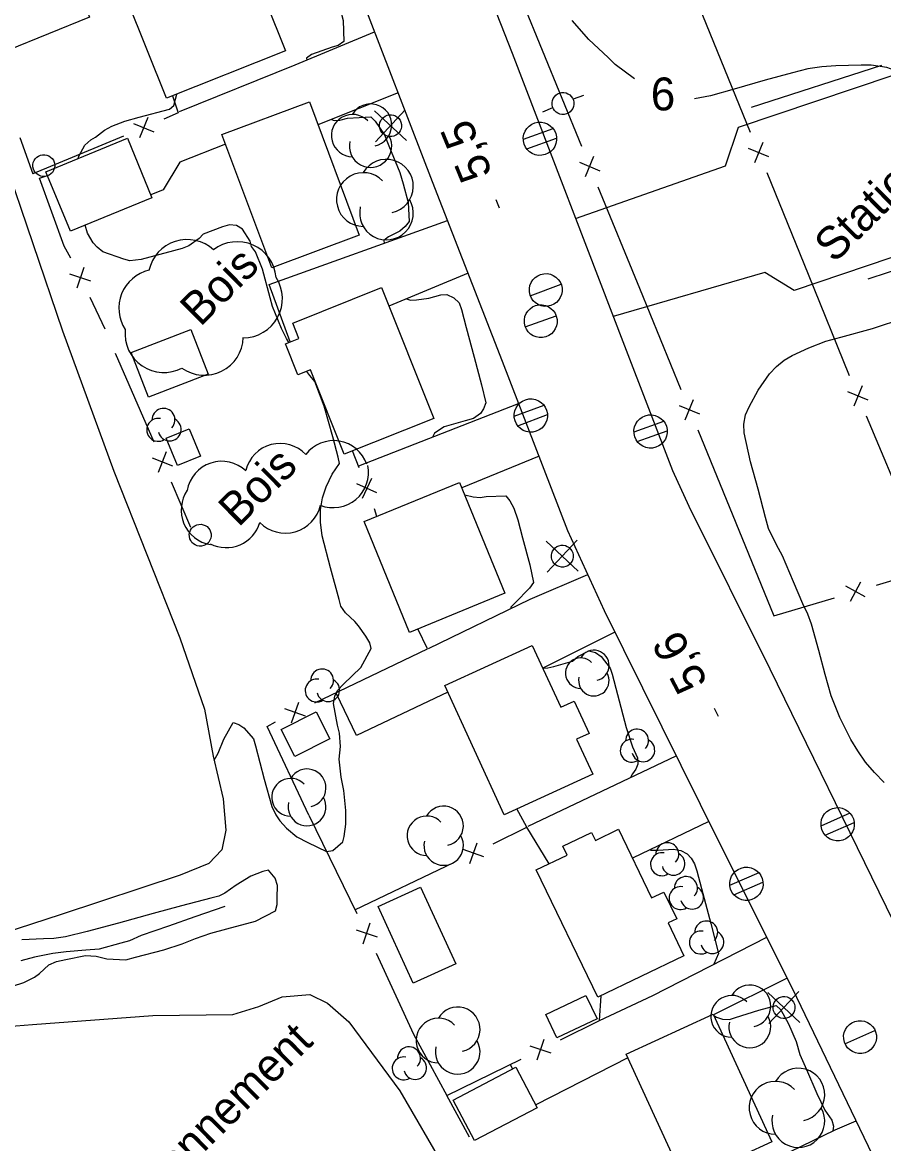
# Model space of a CAD drawing. Extents: x 381879 to 384696, y 5564785 to 5567594.
# Drawn here: x 383743.2 to 383821.8, y 5566686.3 to 5566788.7 of the extents above; entities that cross this region are included whole.
import ezdxf

# ---------------------------------------------------------------- set-up
doc = ezdxf.new("R2010")
doc.units = 0
for name, color, linetype in [('Niveau 19', 7, 'Continuous'), ('Niveau 2', 7, 'Continuous'), ('Niveau 21', 7, 'Continuous'), ('Niveau 3', 7, 'Continuous'), ('Niveau 31', 7, 'Continuous'), ('Niveau 36', 7, 'Continuous'), ('Niveau 37', 7, 'Continuous'), ('Niveau 4', 7, 'Continuous'), ('Niveau 44', 7, 'Continuous'), ('Niveau 52', 7, 'Continuous')]:
    doc.layers.add(name, color=color, linetype=linetype)

msp = doc.modelspace()

# ---------------------------------------------------------------- linework, layer by layer
at = {"layer": 'Niveau 19'}
for points in [[(383757.5, 5566780.56), (383768.08, 5566784.8), (383775.32, 5566787.83)], [(383777.47, 5566782.25), (383770.15, 5566779.33)], [(383761.7, 5566777.57), (383757.54, 5566775.93), (383756.02, 5566773.39), (383754.88, 5566772.94)], [(383767.62, 5566759.51), (383765.69, 5566764.76), (383781.98, 5566770.59)], [(383783.85, 5566765.78), (383776.63, 5566762.76)], [(383773.87, 5566748.19), (383788.46, 5566753.9), (383788.46, 5566753.9)], [(383790.33, 5566749.07), (383783.28, 5566746.18)], [(383780.23, 5566731.51), (383789.52, 5566736.01), (383794.78, 5566738.27)], [(383797.26, 5566733), (383790.67, 5566729.72)], [(383782.01, 5566727.52), (383773.66, 5566723.58), (383771.83, 5566727.38)], [(383789.34, 5566715.29), (383802.86, 5566721.72)], [(383805.84, 5566715.72), (383798.86, 5566712.36)], [(383812.97, 5566701.43), (383806.26, 5566698.06)], [(383798.43, 5566694.14), (383790.03, 5566689.84)], [(383787.91, 5566693.13), (383787.73, 5566693.55)], [(383817.37, 5566687.58), (383819.28, 5566688.39)]]:
    msp.add_lwpolyline(points, dxfattribs=at)
at = {"layer": 'Niveau 2'}
for points in [[(383764.66, 5566792.39), (383765.01, 5566792.5), (383767.2, 5566793.5), (383767.74, 5566793.73), (383768.88, 5566794.04), (383770.46, 5566794.33), (383770.92, 5566793.92), (383771.2, 5566793.42), (383771.41, 5566792.81), (383771.75, 5566791.53), (383772.44, 5566788.86), (383772.5, 5566786.93), (383772, 5566786.57), (383771.44, 5566786.42), (383769.57, 5566785.75), (383769.1, 5566785.42), (383769.12, 5566785.24)], [(383799.03, 5566783.54), (383797.29, 5566784.85), (383796.65, 5566785.47), (383794.88, 5566787.12), (383793.34, 5566788.86)], [(383822.9, 5566783.96), (383822.76, 5566784.32), (383822.09, 5566784.56), (383820.65, 5566784.77), (383819.74, 5566784.78), (383817.41, 5566784.73), (383816.13, 5566784.64), (383814.88, 5566784.45), (383813.46, 5566784.09), (383810.97, 5566783.42), (383808.13, 5566782.58), (383805.97, 5566781.98), (383804.53, 5566781.71)], [(383748.26, 5566776.26), (383748.31, 5566776.47), (383748.86, 5566777.49), (383749.4, 5566777.97), (383749.85, 5566778.21), (383750.65, 5566778.84), (383751.32, 5566779.21), (383752.52, 5566779.67), (383753.82, 5566780.02), (383756.58, 5566780.76), (383756.99, 5566781.1), (383757.15, 5566781.66), (383757.26, 5566782.13)], [(383771.38, 5566779.82), (383771.64, 5566779.72), (383772.15, 5566779.76), (383772.84, 5566779.94), (383774.97, 5566780.05), (383775.36, 5566779.66), (383776.21, 5566778.42), (383776.63, 5566777.4), (383777.61, 5566774.97), (383777.93, 5566773.95), (383778.38, 5566772.25), (383778.46, 5566770.51), (383778.1, 5566770.05), (383777.62, 5566769.63), (383776.59, 5566769.12), (383776.17, 5566768.78), (383776.19, 5566768.52)], [(383767.48, 5566759.45), (383767.26, 5566759.81), (383766.83, 5566760.75), (383766.01, 5566762.73), (383765.79, 5566763.54), (383765.09, 5566766.14), (383764.44, 5566767.73), (383764.08, 5566768.21), (383763.95, 5566768.72), (383763.26, 5566769.82), (383762.7, 5566770.14), (383762.08, 5566770.2), (383761.42, 5566770.03), (383759.66, 5566769.35), (383759.29, 5566768.94), (383758.35, 5566768.29), (383757.75, 5566768.03), (383756.96, 5566767.82), (383754.02, 5566767.03), (383752.96, 5566766.91), (383752.44, 5566767.08), (383750.52, 5566767.75), (383750, 5566768.15), (383749.64, 5566768.55), (383749.11, 5566769.44), (383748.91, 5566770.17)], [(383778.24, 5566763.43), (383778.6, 5566763.33), (383779.13, 5566763.34), (383780.27, 5566763.52), (383781.37, 5566763.82), (383781.92, 5566763.84), (383782.54, 5566763.55), (383783.04, 5566763.07), (383783.24, 5566762.46), (383783.68, 5566760.83), (383784.4, 5566758.13), (383785.08, 5566755.6), (383785.46, 5566753.96), (383785.27, 5566753.41), (383784.98, 5566752.98), (383784.35, 5566752.53), (383783.57, 5566752.29), (383781.66, 5566751.76), (383780.78, 5566751.18), (383780.6, 5566750.82)], [(383821.84, 5566719.29), (383820.95, 5566720.19), (383820.14, 5566721.15), (383819.43, 5566722.16), (383818.8, 5566723.2), (383817.78, 5566725.22), (383817, 5566727.21), (383816.45, 5566729.13), (383815.86, 5566731.33), (383815.21, 5566733.75), (383814.87, 5566734.65), (383814.42, 5566735.61), (383813.57, 5566737.61), (383812.54, 5566739.99), (383812.01, 5566740.98), (383811.28, 5566742.47), (383811.01, 5566743.47), (383810.32, 5566746.06), (383809.64, 5566748.57), (383809.04, 5566751.2), (383809.02, 5566751.99), (383809.18, 5566752.84), (383809.5, 5566753.58), (383810.34, 5566755.09), (383811.37, 5566756.59), (383812, 5566757.26), (383812.71, 5566757.84), (383813.44, 5566758.26), (383814.97, 5566758.98), (383816.51, 5566759.58), (383817.88, 5566759.95), (383820.77, 5566760.75), (383823.71, 5566761.7)], [(383761.55, 5566723.25), (383762.41, 5566724.76), (383762.91, 5566724.58), (383763.37, 5566724.27), (383764.26, 5566723.27), (383764.43, 5566722.63), (383765.24, 5566719.6), (383765.94, 5566717.09), (383766.29, 5566716.32), (383766.66, 5566715.79), (383767.27, 5566715.11), (383768.21, 5566714.33), (383769.22, 5566713.81), (383770.93, 5566712.98), (383771.51, 5566713.06), (383772.41, 5566713.86), (383772.55, 5566714.35), (383772.7, 5566715.49), (383772.68, 5566716.74), (383772.5, 5566718.54), (383772.26, 5566719.78), (383772.09, 5566721.41), (383772.21, 5566722.56), (383772.12, 5566723.78), (383771.92, 5566724.51), (383771.57, 5566726.51), (383771.7, 5566727.17), (383771.94, 5566727.69), (383772.49, 5566728.27), (383774.05, 5566729.78), (383775.01, 5566731.53), (383774.87, 5566732.05), (383774.52, 5566732.64), (383773.86, 5566733.58), (383773.5, 5566733.99), (383772.65, 5566734.77), (383772.24, 5566735.39), (383772.07, 5566736), (383771.3, 5566738.88), (383770.54, 5566741.79), (383770.37, 5566743.04), (383770.39, 5566744.19), (383770.56, 5566745.27), (383770.89, 5566746.29), (383771.45, 5566747.43), (383772.12, 5566748.42), (383771.98, 5566749), (383771.49, 5566750.84), (383770.72, 5566753.64), (383769.86, 5566755.91), (383769.39, 5566756.43), (383769.13, 5566756.81)], [(383783.54, 5566745.56), (383784.3, 5566745.37), (383784.96, 5566745.3), (383785.5, 5566745.4), (383787.3, 5566745.45), (383787.67, 5566745.01), (383788.02, 5566744.34), (383788.38, 5566743.27), (383788.82, 5566741.63), (383789.49, 5566739.16), (383789.83, 5566737.55), (383789.46, 5566737.02), (383788.16, 5566735.68), (383787.75, 5566735.28), (383787.74, 5566735.15)], [(383790.69, 5566729.73), (383791.12, 5566729.74), (383791.67, 5566729.87), (383793.39, 5566730.37), (383793.86, 5566730.79), (383794.88, 5566731.31), (383795.49, 5566731.14), (383795.99, 5566730.8), (383796.82, 5566729.73), (383796.99, 5566729.18), (383797.48, 5566727.33), (383798.29, 5566724.31), (383798.87, 5566722.54), (383799.32, 5566721.54), (383799.35, 5566720.97), (383799.17, 5566720.49)], [(383760.66, 5566721.32), (383761.03, 5566721.95), (383761.55, 5566723.25)], [(383799.17, 5566720.49), (383798.87, 5566720.06), (383798.67, 5566719.73)], [(383800.47, 5566713.14), (383800.53, 5566713.09), (383801.19, 5566713.1), (383802.61, 5566713.21), (383803.27, 5566713.08), (383803.85, 5566712.76), (383804.22, 5566712.38), (383804.51, 5566711.86), (383804.72, 5566711.21), (383805.15, 5566709.61), (383806.01, 5566706.4), (383806.72, 5566703.67), (383806.28, 5566702.69)], [(383741.13, 5566700.32), (383743.3, 5566701.03), (383744.27, 5566701.51), (383744.72, 5566701.84), (383745.58, 5566702.63), (383746.29, 5566702.93), (383747.13, 5566703.13), (383748.94, 5566703.49), (383749.9, 5566703.44), (383750.88, 5566703.18), (383752.61, 5566703.08), (383753.5, 5566703.32), (383756.07, 5566704.01), (383757.74, 5566704.54), (383758.96, 5566705.04), (383760.38, 5566705.54), (383761.84, 5566705.93), (383764.45, 5566706.63), (383766.27, 5566707.57), (383766.41, 5566708.15), (383766.41, 5566708.75), (383766.44, 5566709.88), (383766.24, 5566710.55), (383765.63, 5566711.29), (383765.12, 5566711.16), (383764.02, 5566710.72), (383762.68, 5566709.92), (383761.66, 5566709.18), (383761.11, 5566708.92), (383760.37, 5566708.73), (383757.69, 5566708.01), (383755.1, 5566707.31), (383751.93, 5566706.45), (383749.09, 5566705.68), (383747.09, 5566705.19), (383746.02, 5566705.03), (383745.09, 5566705.01), (383743.11, 5566704.91)], [(383806.29, 5566698), (383806.54, 5566697.85), (383807.07, 5566697.66), (383807.73, 5566697.65), (383808.26, 5566697.83), (383810.4, 5566698.51), (383811.99, 5566698.93), (383812.39, 5566698.52), (383813.1, 5566697.24), (383813.8, 5566695.63), (383814.14, 5566694.44), (383814.75, 5566693.09), (383815.69, 5566690.9), (383816.41, 5566689.37), (383817.07, 5566688.45), (383817.22, 5566687.89), (383817.16, 5566687.48)]]:
    msp.add_lwpolyline(points, dxfattribs=at)
at = {"layer": 'Niveau 21'}
for points in [[(383850.72, 5566624.73), (383846.58, 5566633.04), (383844.03, 5566638.18), (383837.03, 5566652.16), (383829.2, 5566667.73), (383821.17, 5566684.48), (383813.85, 5566699.66), (383805.07, 5566717.27), (383796.29, 5566734.96), (383792.97, 5566742.25), (383786.99, 5566757.71), (383780.6, 5566774.13), (383773.93, 5566791.44), (383765.36, 5566813.53), (383763.67, 5566818.84), (383759.05, 5566837.5), (383754.64, 5566855.96), (383750, 5566874.95)], [(383791.81, 5566832.8), (383787.01, 5566831.22), (383781.1, 5566829.23), (383779.33, 5566828.36), (383777.97, 5566827.25), (383776.99, 5566826.12), (383776.21, 5566824.85), (383775.55, 5566823.76), (383775.09, 5566822.09), (383774.9, 5566820.07), (383775.27, 5566818.22), (383776.8, 5566814.22), (383781.48, 5566802.16), (383787.86, 5566785.86), (383798.14, 5566759.15), (383802.52, 5566747.76), (383804.01, 5566744.51), (383811.39, 5566729.65), (383822.03, 5566707.93), (383829.3, 5566692.96), (383837.77, 5566676.26)]]:
    msp.add_lwpolyline(points, dxfattribs=at)
at = {"layer": 'Niveau 3'}
for p, q in [((383786.72, 5566771.73), (383786.42, 5566772.48)), ((383806.71, 5566725.31), (383806.35, 5566726.03))]:
    msp.add_line(p, q, dxfattribs=at)
at = {"layer": 'Niveau 31'}
for points in [[(383752.74, 5566790.73), (383763.59, 5566795.07), (383767.17, 5566786.1), (383756.32, 5566781.76)], [(383739.66, 5566791.43), (383747.14, 5566794.47), (383749.3, 5566789.15), (383741.82, 5566786.11)], [(383769.36, 5566781.44), (383773.92, 5566769.26), (383765.93, 5566766.27), (383761.37, 5566778.45)], [(383754.99, 5566772.68), (383747.55, 5566769.61), (383745.31, 5566775.04), (383752.75, 5566778.11)], [(383775.95, 5566764.47), (383780.71, 5566752.53), (383772.55, 5566749.26), (383769.47, 5566756.95), (383768.32, 5566756.49), (383767.18, 5566759.33), (383768.41, 5566759.82), (383767.84, 5566761.23)], [(383753.09, 5566758.55), (383758.54, 5566760.65), (383760.12, 5566756.56), (383754.67, 5566754.46)], [(383756.29, 5566750.71), (383758.4, 5566751.58), (383759.43, 5566749.09), (383757.32, 5566748.22)], [(383783.08, 5566746.68), (383787.21, 5566736.57), (383778.49, 5566732.99), (383774.35, 5566743.1)], [(383787.15, 5566716.34), (383781.72, 5566728.14), (383789.71, 5566731.8), (383792.31, 5566726.16), (383793.54, 5566726.72), (383794.9, 5566723.76), (383793.76, 5566723.24), (383795.23, 5566720.05)], [(383766.78, 5566724.12), (383769.97, 5566725.73), (383771.22, 5566723.26), (383768.03, 5566721.65)], [(383795.7, 5566699.67), (383790.08, 5566711.3), (383792.9, 5566712.66), (383792.51, 5566713.47), (383795.13, 5566714.73), (383795.48, 5566714), (383797.58, 5566715.01), (383800.6, 5566708.75), (383801.72, 5566709.28), (383802.9, 5566706.84), (383802.12, 5566706.46), (383803.56, 5566703.47)], [(383779.52, 5566709.74), (383782.73, 5566702.73), (383778.85, 5566700.95), (383775.64, 5566707.96)], [(383790.94, 5566698.1), (383794.6, 5566699.84), (383795.62, 5566697.7), (383791.96, 5566695.96)], [(383803.65, 5566682.81), (383798.28, 5566694.47), (383806.23, 5566698.13), (383811.59, 5566686.46)], [(383782.49, 5566690.29), (383788.22, 5566693.29), (383790.16, 5566689.59), (383784.43, 5566686.59)]]:
    msp.add_lwpolyline(points, close=True, dxfattribs=at)
at = {"layer": 'Niveau 36'}
for p, q in [((383794.38, 5566782.02), (383793.45, 5566781.66)), ((383775.4, 5566777.79), (383778.12, 5566780.71)), ((383790.67, 5566780.53), (383791.59, 5566780.92)), ((383775.3, 5566780.61), (383778.22, 5566777.89)), ((383791.6, 5566778.98), (383788.87, 5566778)), ((383789.2, 5566777.14), (383791.93, 5566778.12)), ((383789.52, 5566763.73), (383792.34, 5566764.77)), ((383789.06, 5566760.9), (383791.88, 5566761.9)), ((383790.76, 5566753.72), (383788.04, 5566752.71)), ((383788.38, 5566751.86), (383791.1, 5566752.87)), ((383801.7, 5566752.24), (383798.97, 5566751.28)), ((383799.3, 5566750.42), (383802.03, 5566751.38)), ((383790.98, 5566741.31), (383793.9, 5566738.59)), ((383791.08, 5566738.49), (383793.8, 5566741.41)), ((383818.71, 5566716.47), (383816.06, 5566715.3)), ((383816.45, 5566714.47), (383819.1, 5566715.64)), ((383810.39, 5566711.03), (383807.73, 5566709.87)), ((383808.11, 5566709.03), (383810.77, 5566710.19)), ((383811.22, 5566700.1), (383814.14, 5566697.38)), ((383811.32, 5566697.28), (383814.04, 5566700.2)), ((383818.25, 5566695.42), (383820.99, 5566696.64))]:
    msp.add_line(p, q, dxfattribs=at)
for centre, major_axis in [((383792.51, 5566781.28), (-0.116, 0.993)), ((383776.77, 5566779.25), (0.116, -0.993)), ((383790.41, 5566778.06), (-0.18, 1.51)), ((383745.12, 5566775.61), (0.116, -0.993)), ((383790.94, 5566764.25), (-0.17, 1.49)), ((383790.48, 5566761.4), (-0.17, 1.49)), ((383789.58, 5566752.79), (-0.18, 1.51)), ((383800.51, 5566751.33), (-0.18, 1.51)), ((383759.4, 5566741.86), (0.116, -0.993)), ((383792.45, 5566739.95), (0.116, -0.993)), ((383817.59, 5566715.47), (-0.18, 1.51)), ((383809.26, 5566710.03), (-0.18, 1.51)), ((383812.69, 5566698.74), (0.116, -0.993)), ((383819.63, 5566696.04), (-0.17, 1.49))]:
    msp.add_ellipse(centre, major_axis=major_axis, ratio=0.99999, dxfattribs=at)
at = {"layer": 'Niveau 37'}
for p, q in [((383809.62, 5566778.64), (383802.81, 5566795.38)), ((383788.83, 5566790.54), (383794.2, 5566777.38)), ((383809.73, 5566780.94), (383821.63, 5566784.77)), ((383754.61, 5566780), (383753.85, 5566778.14)), ((383753.3, 5566779.45), (383755.16, 5566778.69)), ((383742.92, 5566778.17), (383744.12, 5566774.87)), ((383752.39, 5566778.3), (383744.12, 5566774.87)), ((383810.77, 5566777.71), (383809.99, 5566775.86)), ((383811.31, 5566776.4), (383809.46, 5566777.18)), ((383794.03, 5566775.92), (383795.88, 5566775.14)), ((383794.57, 5566774.6), (383795.34, 5566776.46)), ((383814.92, 5566765.68), (383811.14, 5566774.94)), ((383795.71, 5566773.68), (383799.49, 5566764.42)), ((383820.37, 5566765.26), (383834.42, 5566769.95)), ((383749.41, 5566765.05), (383747.51, 5566765.69)), ((383748.78, 5566766.32), (383748.14, 5566764.42)), ((383799.49, 5566764.42), (383803.28, 5566755.17)), ((383750.72, 5566760.66), (383749.35, 5566763.58)), ((383751.62, 5566758.48), (383755.15, 5566750.4)), ((383819.82, 5566755.5), (383819.06, 5566753.64)), ((383803.66, 5566752.39), (383804.44, 5566754.24)), ((383820.37, 5566754.19), (383818.51, 5566754.95)), ((383803.12, 5566753.7), (383804.97, 5566752.93)), ((383826.07, 5566738.79), (383820.22, 5566752.72)), ((383804.81, 5566751.47), (383811.76, 5566734.5)), ((383755.58, 5566747.63), (383756.32, 5566749.5)), ((383773.91, 5566748.01), (383773.3, 5566749.56)), ((383755.01, 5566748.93), (383756.88, 5566748.2)), ((383775.03, 5566747.05), (383774.19, 5566745.22)), ((383756.75, 5566746.73), (383758.52, 5566742.6)), ((383775.52, 5566745.72), (383773.7, 5566746.55)), ((383775.53, 5566743.58), (383775.31, 5566744.26)), ((383821.14, 5566737.3), (383826.07, 5566738.79)), ((383820.11, 5566736.25), (383818.34, 5566737.2)), ((383818.75, 5566735.84), (383819.7, 5566737.61)), ((383811.76, 5566734.5), (383817.31, 5566736.15)), ((383767.73, 5566724.73), (383768.39, 5566726.62)), ((383769.01, 5566725.35), (383767.11, 5566726.01)), ((383769.32, 5566716.29), (383773.71, 5566707.31)), ((383785.29, 5566712.49), (383783.4, 5566713.16)), ((383784.01, 5566711.88), (383784.68, 5566713.78)), ((383773.51, 5566707.67), (383782.54, 5566711.97)), ((383774.26, 5566704.56), (383774.91, 5566706.46)), ((383773.64, 5566705.83), (383775.54, 5566705.18)), ((383790.16, 5566693.95), (383790.81, 5566695.85)), ((383791.43, 5566694.57), (383789.53, 5566695.22)), ((383781.92, 5566690.69), (383788.69, 5566694.02)), ((383783.99, 5566686.89), (383781.92, 5566690.69))]:
    msp.add_line(p, q, dxfattribs=at)
for points in [[(383756.88, 5566781.98), (383757.4, 5566780.42), (383756.08, 5566779.84)], [(383747.58, 5566767.17), (383746.99, 5566768.25), (383744.73, 5566774.46), (383745.45, 5566774.71)], [(383818.67, 5566756.41), (383814.92, 5566765.68)], [(383769.86, 5566726.55), (383780.14, 5566731.48), (383779.27, 5566733.31)], [(383769.32, 5566716.29), (383765.51, 5566724.41), (383766.26, 5566724.81)], [(383791.25, 5566711.86), (383789.22, 5566715.21), (383788.31, 5566716.87)], [(383786.15, 5566713.69), (383789.22, 5566715.21)], [(383795.84, 5566697.55), (383800.71, 5566699.84), (383811.11, 5566705.16)], [(383775.47, 5566703.71), (383778.86, 5566696.29), (383781.92, 5566690.69)], [(383792.28, 5566695.78), (383795.84, 5566697.55), (383795.99, 5566699.81)], [(383805.26, 5566681.7), (383817.37, 5566687.58)]]:
    msp.add_lwpolyline(points, dxfattribs=at)
at = {"layer": 'Niveau 4'}
msp.add_lwpolyline([(383761.65, 5566707.95), (383758.92, 5566707.03), (383756.5, 5566706.17), (383754, 5566705.3), (383752.94, 5566704.83), (383752.16, 5566704.6), (383750.16, 5566704.08), (383748.95, 5566703.96), (383747.17, 5566703.82), (383745.95, 5566703.66), (383744.26, 5566703.33), (383743.02, 5566703)], dxfattribs=at)
at = {"layer": 'Niveau 44'}
for centre, radius, start, end in [((383774.95, 5566779.31), 1.93, 282.2692, 149.7262), ((383773.3, 5566778.35), 1.93, 44.1153, 269.8039), ((383774.95, 5566777.38), 1.93, 166.9368, 29.6212), ((383776.4, 5566773.73), 2.45, 282.2692, 149.7262), ((383774.29, 5566772.51), 2.45, 44.1153, 269.8039), ((383776.4, 5566771.28), 2.45, 166.9368, 29.6212), ((383758.19, 5566765.31), 3.55, 47.1087, 168.0922), ((383762.79, 5566765.12), 3.54, 4.3008, 128.0107), ((383755.52, 5566762.59), 3.55, 103.0377, 213.4048), ((383763.34, 5566763.45), 3.56, 269.8037, 32.9847), ((383756.08, 5566760.27), 3.55, 174.1444, 297.6622), ((383759.78, 5566760.02), 3.55, 234.6453, 358.0557), ((383794.13, 5566729.27), 1.39, 44.1153, 269.8039), ((383795.33, 5566729.97), 1.39, 282.2692, 149.7262), ((383795.33, 5566728.58), 1.39, 166.9368, 29.6212), ((383769.15, 5566718.79), 1.73, 282.2692, 149.7262), ((383767.66, 5566717.93), 1.73, 44.1153, 269.8039), ((383769.15, 5566717.06), 1.73, 166.9368, 29.6212), ((383780.08, 5566714.42), 1.8, 44.1153, 269.8039), ((383781.62, 5566715.32), 1.8, 282.2692, 149.7262), ((383781.62, 5566713.52), 1.8, 166.9368, 29.6212), ((383807.92, 5566697.93), 1.91, 44.1153, 269.8039), ((383809.57, 5566698.88), 1.91, 282.2692, 149.7262), ((383782.9, 5566696.74), 2.04, 282.2692, 149.7262), ((383809.57, 5566696.97), 1.91, 166.9368, 29.6212), ((383781.15, 5566695.72), 2.04, 44.1153, 269.8039), ((383782.9, 5566694.7), 2.04, 166.9368, 29.6212), ((383814, 5566690.78), 2.41, 282.2692, 149.7262), ((383811.92, 5566689.58), 2.41, 44.1153, 269.8039), ((383814, 5566688.37), 2.41, 166.9368, 29.6212)]:
    msp.add_arc(centre, radius, start, end, dxfattribs=at)
for centre, major_axis, ratio, start_param, end_param in [((383756.05, 5566752.4), (0.12, -1.04), 0.99999, 0.690957, 4.629966), ((383755.56, 5566751.48), (0.12, -1.04), 0.99999, 2.834597, 6.721173), ((383756.61, 5566751.52), (0.12, -1.04), 0.99999, 4.847526, 8.817401), ((383766.69, 5566747.03), (-2.45, -2.08), 0.999316, 3.191878, 5.342164), ((383771.58, 5566747.3), (-2.81, -1.53), 0.998926, 2.97358, 5.136373), ((383761.37, 5566745.4), (-3.05, -1.01), 0.999367, 3.635985, 5.788793), ((383771.54, 5566747.59), (2.46, 2.07), 0.99956, 3.637044, 5.787734), ((383760.87, 5566744.16), (1.48, -2.85), 0.999929, 3.63806, 5.62558), ((383767.17, 5566745.34), (0.9, -3.16), 0.999994, 5.218353, 7.348828), ((383761.77, 5566743.93), (3.14, 0.64), 0.999373, 4.040676, 5.792713), ((383770.52, 5566728.6), (0.12, -1.04), 0.99999, 0.690957, 4.629966), ((383770.03, 5566727.68), (0.12, -1.04), 0.99999, 2.834597, 6.721173), ((383771.08, 5566727.72), (0.12, -1.04), 0.99999, 4.847526, 8.817401), ((383799.28, 5566723.11), (0.12, -1.04), 0.99999, 0.690957, 4.629966), ((383798.79, 5566722.19), (0.12, -1.04), 0.99999, 2.834597, 6.721173), ((383799.84, 5566722.23), (0.12, -1.04), 0.99999, 4.847526, 8.817401), ((383802.04, 5566712.74), (0.12, -1.04), 0.99999, 0.690957, 4.629966), ((383801.55, 5566711.82), (0.12, -1.04), 0.99999, 2.834597, 6.721173), ((383802.6, 5566711.86), (0.12, -1.04), 0.99999, 4.847526, 8.817401), ((383803.74, 5566709.65), (0.12, -1.04), 0.99999, 0.690957, 4.629966), ((383803.25, 5566708.73), (0.12, -1.04), 0.99999, 2.834597, 6.721173), ((383804.3, 5566708.77), (0.12, -1.04), 0.99999, 4.847526, 8.817401), ((383805.59, 5566705.59), (0.12, -1.04), 0.99999, 0.690957, 4.629966), ((383805.1, 5566704.67), (0.12, -1.04), 0.99999, 2.834597, 6.721173), ((383806.15, 5566704.71), (0.12, -1.04), 0.99999, 4.847526, 8.817401), ((383778.46, 5566694.1), (0.12, -1.04), 0.99999, 0.690957, 4.629966), ((383777.97, 5566693.18), (0.12, -1.04), 0.99999, 2.834597, 6.721173), ((383779.02, 5566693.22), (0.12, -1.04), 0.99999, 4.847526, 8.817401)]:
    msp.add_ellipse(centre, major_axis=major_axis, ratio=ratio, start_param=start_param, end_param=end_param, dxfattribs=at)
at = {"layer": 'Niveau 52'}
for points in [[(383793.66, 5566770.78), (383807.35, 5566775.6), (383808.54, 5566779.13), (383829.71, 5566786.25), (383836, 5566788.26)], [(383741.4, 5566776.46), (383746.84, 5566760.51), (383751.51, 5566747.72), (383757.54, 5566732.48), (383759.8, 5566725.97), (383760.58, 5566721.68), (383761.48, 5566717.78), (383761.74, 5566714.93), (383761.38, 5566713.14), (383760.17, 5566711.9), (383757.57, 5566710.81), (383746.7, 5566707.24), (383732, 5566702.45)], [(383848.31, 5566775.84), (383829.01, 5566769.4), (383813.63, 5566764.22), (383810.94, 5566765.84), (383797.1, 5566761.84)], [(383709.13, 5566685.56), (383717.28, 5566690.11), (383722.97, 5566692.97), (383728.11, 5566694.67), (383737.2, 5566696.65), (383744.08, 5566697.19), (383755.06, 5566698.02), (383762.39, 5566698.1), (383764.74, 5566698.84), (383766.88, 5566699.72), (383769.41, 5566699.94), (383771.03, 5566699.15), (383772.98, 5566697.44), (383777.63, 5566691.13), (383781.79, 5566683.96), (383784.6, 5566677.96), (383788.41, 5566669.38), (383792.38, 5566660.28), (383795.83, 5566654.26), (383799, 5566648.61), (383799.89, 5566645.91)]]:
    msp.add_lwpolyline(points, dxfattribs=at)

# ---------------------------------------------------------------- texts
at = {"layer": 'Niveau 2'}
msp.add_text('6', height=3, rotation=0.0003, dxfattribs=at).set_placement((383800.53, 5566780.65))
at = {"layer": 'Niveau 3'}
for s, rotation, p in [('5,5', 112.2959, (383786.11, 5566774.89)), ('5,6', 117.7611, (383805.79, 5566728.44))]:
    msp.add_text(s, height=3, rotation=rotation, dxfattribs=at).set_placement(p)
at = {"layer": 'Niveau 44'}
for p in [(383759.4, 5566760.82), (383762.89, 5566742.52)]:
    msp.add_text('Bois', height=3, rotation=44.7707, dxfattribs=at).set_placement(p)
at = {"layer": 'Niveau 52'}
for height, rotation, p in [(2.9999, 44.7707, (383817.28, 5566766.62)), (3, 44.7717, (383751.48, 5566677.27))]:
    msp.add_text('Stationnement', height=height, rotation=rotation, dxfattribs=at).set_placement(p)

doc.saveas('drawing.dxf')
